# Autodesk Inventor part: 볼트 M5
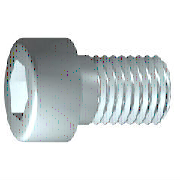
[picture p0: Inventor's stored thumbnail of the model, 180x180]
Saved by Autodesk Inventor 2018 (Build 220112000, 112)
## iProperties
IsCustomPart: 1
Created: 2012-02
Part Number: 볼트 M5
Material: 강철, 연강
Description: 6각머리 태핑 나사
Document SubType Name: Modeling
Standard: KS B 1003
Designer: mduedu
Standards Organization: KS
Language: ko-KR
Size Designation: M 5 x 16
Categories: <MemberInstance><Categories><Category DisplayName="조임쇠" InternalName="e4da775c-781d-43d5-af7c-5136215cf5a6" Mnemonic="FSTN"><Category DisplayName="볼트" InternalN
Density: 1 g/cm^3
Appearance: 강철
Author: mduedu
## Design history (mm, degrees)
sketch "스케치1"
  geometry: L1 (-1.167, 0)-(16, 0); L2 (16, 0)-(16, 2.5); L3 (16, 2.5)-(2, 2.5); L4 (2, 2.5)-(1.509, 2.5); L5 (1.509, 2.5)-(0, 2.5); L6 (0, 2.5)-(0, 4.25); L7 (0, 4.25)-(-5, 4.25); L8 (-5, 4.25)-(-5, 2.309); L9 (-5, 2.309)-(-2.5, 2.309); L10 (-2.5, 2.309)-(-1.167, 0); L11 (-9.2, 0)-(20.2, 0) reference; L12 (0, -0.85)-(0, 5.1) reference; L13 (2, 2.5)-(0, 2.5)
  constraints: 22 end point, 6 parallel, 2 collinear, 2 perpendicular, 1 horizontal, 1 point on line
  dimensions: "d1" = 14 distance from line of L3.end L2 (= GEL); "d2" = 0.49086 distance of L4.end L3.end (computed from GAL); "d3" = 5 distance between parallel lines of L8 L6 (= KOH); "d4" = 2.5 distance of L8.end L9.end (= INTI); "d5" = 60 deg angle of L10 L1; "d6" = 5 diameter of L3 L1 (= GD); "d7" = 5 diameter of L5 L1 (= BDM); "d8" = 4.6188 diameter of L9 L1 (= 1.1547 x SW); "d9" = 8.5 diameter of L7 L1 (= KOD); "d26" = 16 distance between parallel lines of L12 L2 (= NLG)
revolve "본체" sketch "스케치1" stored, may be unused: angle "d10" = 90 deg
sketch "스케치2"
  geometry: L1 (0, -5.95)-(0, 5.95) reference; L2 (-5.95, 0)-(5.95, 0) reference; L3 (2.309, 0)-(1.155, -2); L4 (1.155, -2)-(-1.155, -2); L5 (-1.155, -2)-(-2.309, 0); L6 (-2.309, 0)-(-1.155, 2); L7 (-1.155, 2)-(1.155, 2); L8 (1.155, 2)-(2.309, 0); 2 further points
  constraints: 12 end point, 1 coincident, 1 horizontal alignment, 1 point on line, 12 other
extrude "슬롯" join sketch "스케치2" stored distance "d11" = 10; taper "d12" = 0 deg
workplane "Work Plane1"
fillet "Fillet2" dims "d30" = 0.1 (= R)
body "Solid1"
fillet "모깎기1" dims "d17" = 0.5 (= RR)
feature "스레드" dims "d13" = 14 (= GEL), "d14" = 0
chamfer "모따기1" distance "d15" = 0.49076 (= -0.5 x SPD + 0.5 x GD); stored, may be unused: second distance "d16" = 0.49076 (= GUL), angle "d27" = 45 deg
other parameters: "GD" = 5 (= NND) [user parameter; used in 2 equation terms], "NLG" = 16 [user parameter; used in 1 equation term], "GEL" = 14 [user parameter; used in 2 equation terms], "KOD" = 8.5 [user parameter; used in 1 equation term], "KOH" = 5 [user parameter; used in 1 equation term], "INTI" = 2.5 [user parameter; used in 1 equation term], "GAL" = 0.49076 (= 0.61345 x PTC) [user parameter; used in 1 equation term], "GUL" = 0.49076 (= 0.61345 x PTC) [user parameter; used in 1 equation term], "BDM" = 5 (= NND) [user parameter; used in 1 equation term], "SW" = 4 [user parameter; used in 2 equation terms], "RR" = 0.5 [user parameter; used in 1 equation term], "SPD" = 4.01848 (= NND - 1.2269 x PTC) [user parameter; used in 1 equation term], "d19" = 0, "d28" = 0, "d29" = 0, "R" = 0.1 [user parameter; used in 1 equation term], "PHH" = 0.2 [user parameter], "GD1" = 4.01848 (= THREADDIA - 1.2269 x PTC) [user parameter], "THREADDIA" = 5 [user parameter; used in 1 equation term], "FAWI" = 45 deg [user parameter], "TPU" = 12.5 (computed from PTC) [user parameter], "PTC" = 0.8 [user parameter; used in 5 equation terms], "NND" = 5 [user parameter; used in 3 equation terms], "TOA" = 30 deg [user parameter], "E0" = 4.62 (= 1.155 x SW) [user parameter]
